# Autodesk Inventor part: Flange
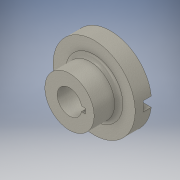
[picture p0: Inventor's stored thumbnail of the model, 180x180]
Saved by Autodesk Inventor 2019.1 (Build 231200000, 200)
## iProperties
Created: 2020-03
Part Number: Flange
Material: Steel, Alloy
Document SubType Name: Modeling
Designer: Oghenemarho
Density: 7.73 g/cm^3
Appearance: Steel - Cast
Author: Oghenemarho
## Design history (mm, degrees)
sketch "Sketch1"
  geometry: L1 (50.8, 0)-(15.24, 0) reference; L2 (15.24, 0)-(15.24, 50.8); L3 (15.24, 50.8)-(30.48, 50.8); L4 (30.48, 50.8)-(30.48, 20.32); L5 (30.48, 20.32)-(50.8, 20.32); L6 (50.8, 20.32)-(50.8, 0); L7 (0, 0)-(0, 74.18)
  constraints: 14 end point, 5 perpendicular, 2 horizontal, 1 vertical
  dimensions: "d0" = 101.6 diameter of L6 L7; "d1" = 60.96 diameter of L4 L7; "d2" = 30.48 diameter of L2 L7; "d3" = 20.32 distance between parallel lines of L1 L5; "d4" = 50.8 distance between parallel lines of L1 L3
revolve "Revolution1" sketch "Sketch1" stored, may be unused: angle "d5" = 90 deg
sketch "Sketch2"
  geometry: L1 (-52.07, -5.994)-(52.07, -5.994); L2 (52.07, -5.994)-(52.07, 5.994); L3 (52.07, 5.994)-(-52.07, 5.994); L4 (-52.07, 5.994)-(-52.07, -5.994); L5 (-52.07, -5.994)-(52.07, 5.994); L6 (52.07, -5.994)-(-52.07, 5.994); 1 further point
  constraints: 12 end point, 2 midpoint, 2 parallel, 1 horizontal, 1 perpendicular
  dimensions: "d6" = 104.14 distance of L3.end L2.end; "d7" = 11.9888 distance of L2.end L1.end
extrude "Extrusion1" cut sketch "Sketch2" distance "d8" = 10.16; taper "d9" = 0 deg
sketch "Sketch3"
  geometry: L1 (14.942, -2.997)-(19.697, -2.997); L2 (19.697, -2.997)-(19.697, 2.997); L3 (50.445, 5.994)-(14.012, 5.994) reference; L4 (19.697, 2.997)-(14.942, 2.997); A1 r 15.24 centre (0, 0) between (14.942, -2.997) and (14.942, 2.997); 1 further point
  constraints: 6 end point, 2 perpendicular, 2 point on circle, 1 centre point, 1 coincident, 1 horizontal, 1 parallel
  dimensions: "d10" = 5.9944 distance of L1.end L2.end; "d11" = 4.75442 distance of L1.start L1.end; "d12" = 30.48 diameter of A1
extrude "Extrusion2" cut sketch "Sketch3" extent not by distance; stored distance "d13" = 10.16; taper "d14" = 0 deg
fillet "Fillet1" dims "d15" = 5.08
body "Solid1"
